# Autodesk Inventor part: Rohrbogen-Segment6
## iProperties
Created: 2006-10
Part Number: Rohrbogen-Segment6
Cost Center: 6,96 kg
Material: 1.4301 (X5CrNi18 10)
Document SubType Name: Sheet Metal
Designer: grote
Authority: 870026 mm^3
Manufacturer: Standard
Standards Organization: Custom
Objekthöhe: 10,000 mm
SaveDate: 2006-10-11
SaveTime: 08:22
FileName: Rohrbogen-Segment
TotalMass: 6,96 kg
TotalVolume: 870026 mm^3
SM_Thickness: 10 mm
SM_Style: NIRO-V80(t =4-10 mm)
SM_Extents: 483,901 mm x 442,368 mm
SM_Square: 214062 mm²
SM_Extents_Width: 483,901 mm
SM_Extents_Length: 442,368 mm
Author: grote
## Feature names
1. Trennen1
2. Trennen2
3. Abgeleiteter Körper1 [Tagging]
4. ExtrusionAbwicklung1
